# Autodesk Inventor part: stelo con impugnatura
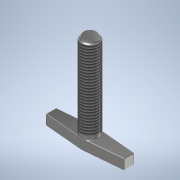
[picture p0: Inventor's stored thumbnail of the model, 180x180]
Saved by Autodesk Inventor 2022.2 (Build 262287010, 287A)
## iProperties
Created: 2014-01
Part Number: stelo con impugnatura
Document SubType Name: Modeling
Designer: UTENTE
Density: 8 g/cm^3
Material: Acciaio inossidabile
Appearance: Semilucidato
Author: UTENTE
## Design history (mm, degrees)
sketch "Schizzo1"
  geometry: L1 (22.5, 0)-(22.5, -3); L2 (22.5, -3)-(0.447, -4.98); L3 (22.5, 3)-(0.447, 4.98); L4 (22.5, 0)-(22.5, 3); L5 (-22.5, 3)-(-0.447, 4.98); L6 (-22.5, -3)-(-0.447, -4.98); L7 (-22.5, 0)-(-22.5, -3); L8 (-22.5, 0)-(-22.5, 3); A1 r 5 centre (0, 0) between (-0.447, -4.98) and (0.447, -4.98); A2 r 5 centre (0, 0) between (0.447, 4.98) and (-0.447, 4.98); 1 further point
  constraints: 16 end point, 4 point on circle, 2 centre point, 1 coincident, 1 tangent
extrude "Estrusione1" new body sketch "Schizzo1" distance "d3" = 6; taper "d4" = 0 deg
sketch "Schizzo2"
  geometry: C1 r 5 at (0, 0); A1 r 5 centre (0, 0) between (-0.447, -4.98) and (0.447, -4.98) reference
  constraints: 1 centre point, 1 coincident
  dimensions: "d5" = 10 diameter of C1
extrude "Estrusione2" join sketch "Schizzo2" distance "d6" = 49; taper "d7" = 0 deg
sketch "Schizzo3"
  geometry: C1 r 5 at (0, 0) reference; C2 r 3.5 at (0, 0)
  constraints: 1 centre point, 1 coincident
extrude "Estrusione3" cut sketch "Schizzo3" distance "d9" = 2; taper "d10" = 0 deg
fillet "Raccordo1" dims "d11" = 1.5
feature "Filettatura1" dims "d12" = 45, "d13" = 0
fillet "Raccordo2" dims "d14" = 0.5
node "Solido1"
